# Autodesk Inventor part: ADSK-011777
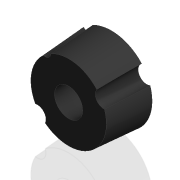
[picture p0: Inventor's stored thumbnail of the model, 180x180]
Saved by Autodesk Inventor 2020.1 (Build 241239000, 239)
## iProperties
Created: 1999-11
Part Number: ADSK-011777
Description: BUSHING,T/L,1.000B,2.250
Document SubType Name: Modeling
Designer: dmcquary
Material: Acier doux
Density: 7.86 g/cm^3
Appearance: Rubber-Black
Mass: 269.409 g
Surface Area: 78.6345 cm^2
Volume: 34.276 cm^3
Control State: 0
Master: False
Checked Out: False
Shininess: 60.0
Length Units: 11269
Angle Units: 11279
Time Units: 11290
Mass Units: 11283
Length Display Precision: 3
Angle Display Precision: 2
Compacted: True
Dimensions: 47,6x25x47,6 mm
Mass: 0,269 kg
DocNumber: ADSK-011777.ipt
Folder: 01 - Themengebiete\Simplification\01 - Packaging machine\
VDS_Category: 3D Komponenten
VLT_Material: Acier doux
Density: 0.0
Volumn: 0.0
Area: 0.0
PropertySet Name: Model Information
Author: dmcquary
Revision Number: -
Title: clamp
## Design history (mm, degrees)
node "Solide1"
  node "Extrusion1" dims "d1" = 25, "d2" = -4 deg
  node "Extrusion2" dims "d8" = 25.4, "d9" = 0
  node "Hole3" dims "d45" = 10, "d46" = 9.525, "d47" = 6.35, "d48" = 60 deg, "d49" = 16, "d50" = 118 deg, "d57" = 6
  node "Hole4" dims "d51" = 6.6, "d52" = 9.525, "d53" = 6.35, "d54" = 60 deg, "d55" = 15.875, "d56" = 118 deg, "d58" = 16
sketch "Sketch1"
  geometry: C1 r 23.812 at (0, 0)
  constraints: 1 centre point
  dimensions: "d0" = 47.625 diameter of C1
sketch "Sketch2"
  geometry: L1 (0, 0)-(18.01, 0); L2 (9, -1.5)-(6.5, -1.5); L3 (6.5, -1.5)-(6.5, 1.5); L4 (6.5, 1.5)-(9, 1.5); L5 (9, 1.5)-(9, -1.5); C1 r 23.812 at (0, 0) reference; C2 r 8.25 at (0, 0)
  constraints: 10 end point, 2 coincident, 2 horizontal, 2 parallel, 1 centre point, 1 perpendicular
  dimensions: "d3" = 16.5 diameter of C2; "d37" = 2.5 distance between parallel lines of L5 L3; "d38" = 3 distance between parallel lines of L4 L2; "d39" = 1.5 distance between parallel lines of L1 L2 (= 0.5 x d38); "d40" = 9 distance from line of C1.centre L5
node "Corps solides"
node "Corps surfaciques"
sketch "Sketch7"
  geometry: L1 (-33.338, 0)-(33.338, 0) reference; L2 (0, 0)-(13.658, 19.506); L3 (0, 0)-(-20.622, 11.906); L4 (0, 0)-(18.241, -15.306); A1 r 23.812 centre (0, 0) between (13.658, 19.506) and (-20.622, 11.906) reference; 3 further points
  constraints: 6 end point, 3 coincident, 3 point on circle
  dimensions: "d42" = 55 deg angle of L1 L2; "d43" = 85 deg angle of L2 L3; "d44" = 85 deg angle of L4 L2
